// Mitsubishi GX Works2 project: PLC_MITSU_BUTTON   PLC: FX1S

PROGRAM MAIN
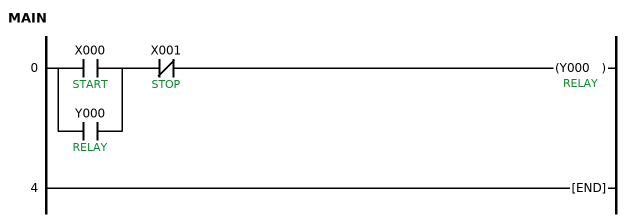
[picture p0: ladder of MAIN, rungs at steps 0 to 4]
0     LD      X000  ; START
      OR      Y000  ; RELAY
      ANI     X001  ; STOP
      OUT     Y000  ; RELAY
4     END
END_PROGRAM
